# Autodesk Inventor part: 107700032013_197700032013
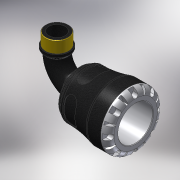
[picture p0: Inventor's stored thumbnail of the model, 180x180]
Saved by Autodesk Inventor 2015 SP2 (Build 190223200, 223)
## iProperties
Created: 2016-12
Part Number: 107700032013_197700032013
Material: PVC-Piping
Description: PLASSON 90° ELBOW WITH MALE INTEGRAL BRASS 32X1.1/4" SERIES 1
Document SubType Name: Modeling
Designer: KIM
Mass: 664.223 g
Surface Area: 733.008 cm^2
Volume: 474.445 cm^3
Density: 1.4 g/cm^3
Appearance: Black Cast
Author: KIM
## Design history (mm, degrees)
derived "1077.ipt"
feature "Solid1::1077.ipt"
tag "TaggingFeature1"
body "Solid1"
other parameters: "d1" = 22.68, "d2" = 32, "d4" = 58, "d8" = 49.3, "d13" = 7.2, "d14" = 7.2, "d15" = 0, "d17" = 360 deg, "d19" = 8 deg, "d20" = 0.64, "d21" = 0.64, "d22" = 8 deg, "d24" = 0, "d26" = 360 deg, "d33" = 5.8, "d43" = 45.24, "d51" = 0.58, "d54" = 11.2, "d55" = 7.04, "d57" = 14.112, "d58" = 0, "d74" = 0, "d78" = 54, "d82" = 0.64, "d115" = 360 deg, "d207" = 90 deg, "d228" = 9.52, "d247" = 1.16, "d248" = 3.24, "d268" = 27.115, "d269" = 3.24, "d270" = 81, "d276" = 41.91, "d278" = 46.101, "d279" = 83, "d280" = 26, "d281" = 6.2865, "d283" = 37.719, "d286" = 0, "d287" = 0, "d288" = 29.337, "d290" = 3.7605, "d292" = 30 deg, "d294" = 4.191, "d296" = 30 deg, "d_" = 32, "E_" = 58, "l_" = 54, "A_" = 81, "A_1" = 83, "R_" = 41.91, "d9" = 9, "d11" = 58, "d289" = 29.337
